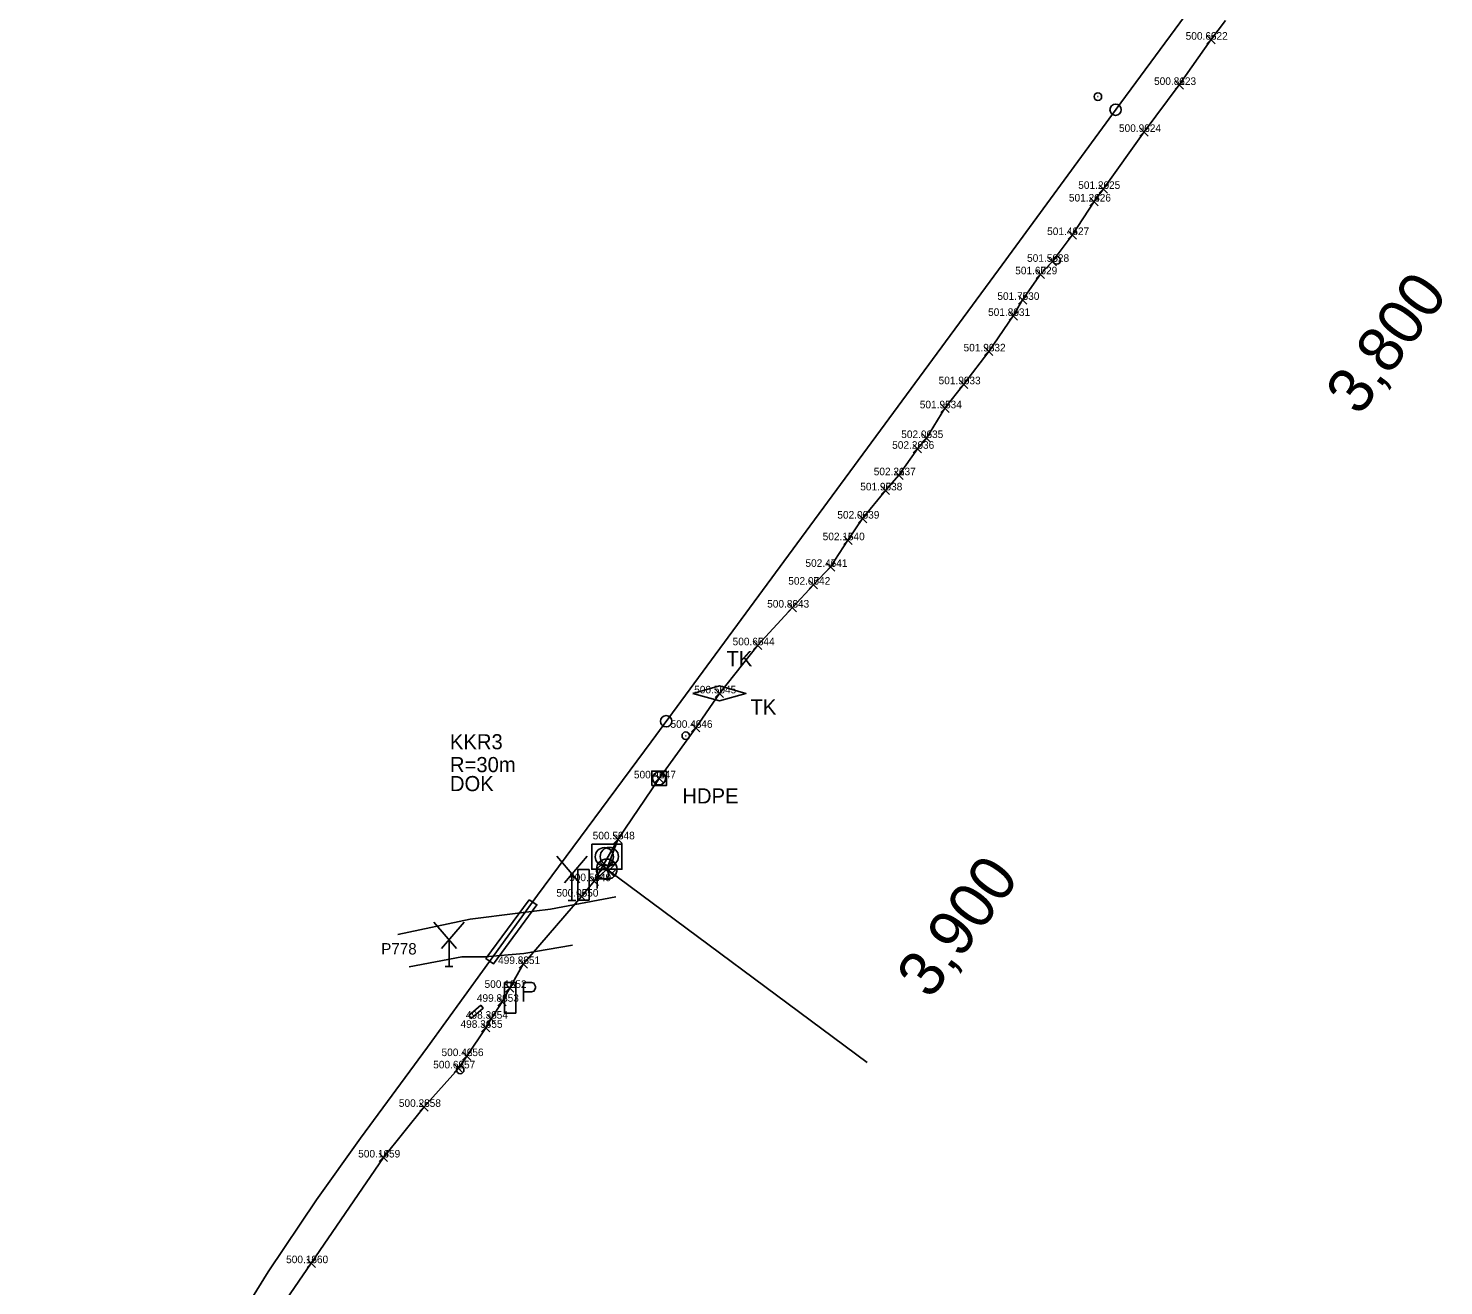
# Model space of a CAD drawing. Extents: x -874058 to -854960, y -10531873 to -1049126.
# Drawn here: x -868334.1 to -868146.9, y -1053927.2 to -1053761 of the extents above; entities that cross this region are included whole.
import ezdxf

# ---------------------------------------------------------------- set-up
doc = ezdxf.new("R2010")
doc.units = 0
for name, color, linetype in [('Vrstva 1', 7, 'Continuous'), ('Vrstva 18', 7, 'Continuous'), ('Vrstva 30', 7, 'Continuous'), ('Vrstva 31', 7, 'Continuous'), ('Vrstva 32', 7, 'Continuous'), ('Vrstva 33', 7, 'Continuous'), ('Vrstva 35', 7, 'Continuous'), ('Vrstva 4', 7, 'Continuous'), ('Vrstva 51', 7, 'Continuous'), ('Vrstva 53', 7, 'Continuous'), ('Vrstva 60', 7, 'Continuous'), ('Vrstva 61', 7, 'Continuous'), ('Vrstva 7', 7, 'Continuous')]:
    doc.layers.add(name, color=color, linetype=linetype)

msp = doc.modelspace()

# ---------------------------------------------------------------- linework, layer by layer
at = {"layer": 'Vrstva 1'}
msp.add_lwpolyline([(-868334.08, -1053989.14), (-868331.21, -1053981.52), (-868326.64, -1053970.33), (-868321.22, -1053958.73), (-868315.73, -1053947.91), (-868309.42, -1053936.78), (-868302.36, -1053925.35), (-868295.97, -1053915.83), (-868290.16, -1053907.67), (-868281.31, -1053895.65), (-868266.75, -1053875.56), (-868251.72, -1053855.3), (-868231.85, -1053828.28), (-868205.77, -1053792.93), (-868190.24, -1053771.67), (-868167.56, -1053740.94)], dxfattribs=at)
at = {"layer": 'Vrstva 18'}
for points in [[(-868275.83, -1053891.48), (-868274.26, -1053890.12)], [(-868275.83, -1053891.48), (-868275.5, -1053891.86), (-868273.93, -1053890.5), (-868274.26, -1053890.12)]]:
    msp.add_lwpolyline(points, dxfattribs=at)
at = {"layer": 'Vrstva 30'}
msp.add_lwpolyline([(-868251.63, -1053861.09), (-868249.71, -1053861.09), (-868249.71, -1053859.17), (-868251.63, -1053859.17)], close=True, dxfattribs=at)
msp.add_circle((-868250.67, -1053860.13), 0.864, dxfattribs=at)
at = {"layer": 'Vrstva 31'}
for p, q in [((-868258.94, -1053872.14), (-868258.26, -1053871.46)), ((-868258.77, -1053872.78), (-868257.86, -1053871.87)), ((-868258.12, -1053871.74), (-868257.58, -1053872.14)), ((-868257.36, -1053872.36), (-868256.44, -1053871.44)), ((-868256.64, -1053871.18), (-868256.64, -1053871.18)), ((-868256.64, -1053871.18), (-868256.64, -1053871.18)), ((-868258.56, -1053873.09), (-868258.56, -1053873.09)), ((-868258.56, -1053873.09), (-868258.56, -1053873.09)), ((-868256.96, -1053872.76), (-868256.25, -1053872.05)), ((-868256.63, -1053873.09), (-868256.63, -1053873.09))]:
    msp.add_line(p, q, dxfattribs=at)
for points in [[(-868258.54, -1053871.18), (-868257.6, -1053872.14), (-868258.56, -1053873.09)], [(-868256.64, -1053871.18), (-868257.59, -1053872.14), (-868256.63, -1053873.09)]]:
    msp.add_lwpolyline(points, dxfattribs=at)
for centre, start, end in [((-868257.6, -1053872.14), 134.5239, 224.7609), ((-868257.58, -1053872.14), 45.4761, 134.8422), ((-868257.58, -1053872.14), 315.2391, 45.4761), ((-868257.6, -1053872.14), 224.7623, 315.5517)]:
    msp.add_arc(centre, 1.35, start, end, dxfattribs=at)
at = {"layer": 'Vrstva 32'}
msp.add_line((-868257.66, -1053869.31), (-868257.62, -1053869.32), dxfattribs=at)
for points in [[(-868175.77, -1053759.96), (-868177.71, -1053762.5), (-868181.89, -1053768.48), (-868186.53, -1053774.69), (-868191.92, -1053782.22), (-868193.15, -1053783.89), (-868196.03, -1053788.32), (-868198.68, -1053791.86), (-868200.25, -1053793.51), (-868202.61, -1053796.89), (-868203.84, -1053799.01), (-868207.08, -1053803.7), (-868210.38, -1053808.04), (-868212.87, -1053811.22), (-868215.32, -1053815.15), (-868216.52, -1053816.57), (-868218.96, -1053820.07), (-868220.74, -1053822.07), (-868223.77, -1053825.8), (-868225.71, -1053828.66), (-868227.99, -1053832.18), (-868230.26, -1053834.53), (-868233.05, -1053837.56), (-868237.62, -1053842.54), (-868242.7, -1053848.9), (-868245.83, -1053853.45), (-868250.67, -1053860.13), (-868256.12, -1053868.19)], [(-868246.2, -1053848.9), (-868242.7, -1053847.9), (-868239.2, -1053848.9), (-868242.7, -1053849.9), (-868246.2, -1053848.9)], [(-868256.12, -1053868.19), (-868259.24, -1053873.72)], [(-868256.12, -1053868.19), (-868257.58, -1053872.14)], [(-868259.24, -1053873.72), (-868260.92, -1053875.76), (-868268.63, -1053884.67), (-868270.42, -1053887.82), (-868271.44, -1053889.66), (-868272.89, -1053891.9), (-868273.6, -1053893.1), (-868276.11, -1053896.84), (-868277.21, -1053898.46), (-868281.75, -1053903.55), (-868287.13, -1053910.24), (-868296.66, -1053924.21), (-868301.1, -1053930.62), (-868304.54, -1053937.27), (-868305.92, -1053938.83), (-868307.71, -1053941.38), (-868311.9, -1053949.06), (-868314.21, -1053952.75), (-868319.28, -1053963.96), (-868324.77, -1053976.84), (-868327.22, -1053982.17), (-868329.01, -1053985.82), (-868329.51, -1053986.53)], [(-868257.58, -1053872.14), (-868259.24, -1053873.72)]]:
    msp.add_lwpolyline(points, dxfattribs=at)
msp.add_lwpolyline([(-868259.58, -1053868.81), (-868255.59, -1053868.81), (-868255.59, -1053872.14), (-868259.58, -1053872.14)], close=True, dxfattribs=at)
for centre in [(-868257.91, -1053870.49), (-868257.25, -1053870.46)]:
    msp.add_circle(centre, 1.2, dxfattribs=at)
at = {"layer": 'Vrstva 33'}
for points in [[(-868261.42, -1053872.19), (-868259.93, -1053872.19), (-868259.93, -1053876.22), (-868261.42, -1053876.22)], [(-868271.11, -1053887.12), (-868269.62, -1053887.12), (-868269.62, -1053891.15), (-868271.11, -1053891.15)]]:
    msp.add_lwpolyline(points, close=True, dxfattribs=at)
for points in [[(-868258.88, -1053874.69), (-868258.88, -1053872.18)], [(-868258.88, -1053872.18), (-868257.84, -1053872.18)], [(-868257.84, -1053873.42), (-868258.88, -1053873.42)], [(-868257.84, -1053872.18), (-868257.52, -1053872.29), (-868257.3, -1053872.7), (-868257.3, -1053872.92), (-868257.52, -1053873.33), (-868257.84, -1053873.42)], [(-868268.58, -1053889.62), (-868268.58, -1053887.11)], [(-868268.58, -1053887.11), (-868267.53, -1053887.11)], [(-868267.53, -1053888.35), (-868268.58, -1053888.35)], [(-868267.53, -1053887.11), (-868267.22, -1053887.21), (-868267, -1053887.62), (-868267, -1053887.84), (-868267.22, -1053888.26), (-868267.53, -1053888.35)]]:
    msp.add_lwpolyline(points, dxfattribs=at)
at = {"layer": 'Vrstva 35'}
msp.add_lwpolyline([(-868260.92, -1053875.76), (-868268.63, -1053884.67)], dxfattribs=at)
at = {"layer": 'Vrstva 4'}
for p, q in [((-868264.2, -1053870.42), (-868261.2, -1053873.92)), ((-868263.2, -1053873.92), (-868260.2, -1053870.42)), ((-868262.2, -1053876.27), (-868262.2, -1053872.77)), ((-868262.7, -1053876.27), (-868261.7, -1053876.27)), ((-868280.45, -1053879.13), (-868277.45, -1053882.63)), ((-868279.45, -1053882.63), (-868276.45, -1053879.13)), ((-868278.45, -1053884.98), (-868278.45, -1053881.48)), ((-868278.95, -1053884.98), (-868277.95, -1053884.98))]:
    msp.add_line(p, q, dxfattribs=at)
at = {"layer": 'Vrstva 51'}
for points in [[(-868285.22, -1053880.77), (-868275.66, -1053878.75), (-868269.37, -1053877.94), (-868265.03, -1053877.42), (-868256.39, -1053875.8)], [(-868267.84, -1053876.18), (-868273.56, -1053883.93), (-868272.58, -1053884.65), (-868266.82, -1053876.84), (-868267.84, -1053876.18)], [(-868283.72, -1053885.02), (-868276.76, -1053883.74), (-868273.71, -1053883.74), (-868268.56, -1053883.26), (-868262.1, -1053882.19)]]:
    msp.add_lwpolyline(points, dxfattribs=at)
at = {"layer": 'Vrstva 53'}
for p, q in [((-868198.13, -1053791.67), (-868198.03, -1053791.67)), ((-868277.02, -1053898.67), (-868276.92, -1053898.67))]:
    msp.add_line(p, q, dxfattribs=at)
for centre in [(-868198.08, -1053791.67), (-868276.97, -1053898.67)]:
    msp.add_circle(centre, 0.499, dxfattribs=at)
at = {"layer": 'Vrstva 60'}
for p, q in [((-868178.26, -1053763.05), (-868177.16, -1053761.95)), ((-868177.16, -1053763.05), (-868178.26, -1053761.95)), ((-868182.44, -1053769.03), (-868181.34, -1053767.93)), ((-868181.34, -1053769.03), (-868182.44, -1053767.93)), ((-868187.08, -1053775.24), (-868185.98, -1053774.14)), ((-868185.98, -1053775.24), (-868187.08, -1053774.14)), ((-868192.47, -1053782.77), (-868191.37, -1053781.67)), ((-868191.37, -1053782.77), (-868192.47, -1053781.67)), ((-868193.7, -1053784.44), (-868192.6, -1053783.34)), ((-868192.6, -1053784.44), (-868193.7, -1053783.34)), ((-868196.58, -1053788.87), (-868195.48, -1053787.77)), ((-868195.48, -1053788.87), (-868196.58, -1053787.77)), ((-868199.23, -1053792.41), (-868198.13, -1053791.31)), ((-868198.13, -1053792.41), (-868199.23, -1053791.31)), ((-868200.8, -1053794.06), (-868199.7, -1053792.96)), ((-868199.7, -1053794.06), (-868200.8, -1053792.96)), ((-868203.16, -1053797.44), (-868202.06, -1053796.34)), ((-868202.06, -1053797.44), (-868203.16, -1053796.34)), ((-868204.39, -1053799.56), (-868203.29, -1053798.46)), ((-868203.29, -1053799.56), (-868204.39, -1053798.46)), ((-868207.63, -1053804.25), (-868206.53, -1053803.15)), ((-868206.53, -1053804.25), (-868207.63, -1053803.15)), ((-868210.93, -1053808.59), (-868209.83, -1053807.49)), ((-868209.83, -1053808.59), (-868210.93, -1053807.49)), ((-868213.42, -1053811.77), (-868212.32, -1053810.67)), ((-868212.32, -1053811.77), (-868213.42, -1053810.67)), ((-868215.87, -1053815.7), (-868214.77, -1053814.6)), ((-868214.77, -1053815.7), (-868215.87, -1053814.6)), ((-868217.07, -1053817.12), (-868215.97, -1053816.02)), ((-868215.97, -1053817.12), (-868217.07, -1053816.02)), ((-868219.51, -1053820.62), (-868218.41, -1053819.52)), ((-868218.41, -1053820.62), (-868219.51, -1053819.52)), ((-868221.29, -1053822.62), (-868220.19, -1053821.52)), ((-868220.19, -1053822.62), (-868221.29, -1053821.52)), ((-868224.32, -1053826.35), (-868223.22, -1053825.25)), ((-868223.22, -1053826.35), (-868224.32, -1053825.25)), ((-868226.26, -1053829.21), (-868225.16, -1053828.11)), ((-868225.16, -1053829.21), (-868226.26, -1053828.11)), ((-868228.54, -1053832.73), (-868227.44, -1053831.63)), ((-868227.44, -1053832.73), (-868228.54, -1053831.63)), ((-868230.81, -1053835.08), (-868229.71, -1053833.98)), ((-868229.71, -1053835.08), (-868230.81, -1053833.98)), ((-868233.6, -1053838.11), (-868232.5, -1053837.01)), ((-868232.5, -1053838.11), (-868233.6, -1053837.01)), ((-868238.17, -1053843.09), (-868237.07, -1053841.99)), ((-868237.07, -1053843.09), (-868238.17, -1053841.99)), ((-868243.25, -1053849.45), (-868242.15, -1053848.35)), ((-868242.15, -1053849.45), (-868243.25, -1053848.35)), ((-868246.38, -1053854), (-868245.28, -1053852.9)), ((-868245.28, -1053854), (-868246.38, -1053852.9)), ((-868251.22, -1053860.68), (-868250.12, -1053859.58)), ((-868250.12, -1053860.68), (-868251.22, -1053859.58)), ((-868256.67, -1053868.74), (-868255.57, -1053867.64)), ((-868255.57, -1053868.74), (-868256.67, -1053867.64)), ((-868259.79, -1053874.27), (-868258.69, -1053873.17)), ((-868258.69, -1053874.27), (-868259.79, -1053873.17)), ((-868261.47, -1053876.31), (-868260.37, -1053875.21)), ((-868260.37, -1053876.31), (-868261.47, -1053875.21)), ((-868269.18, -1053885.22), (-868268.08, -1053884.12)), ((-868268.08, -1053885.22), (-868269.18, -1053884.12)), ((-868270.97, -1053888.37), (-868269.87, -1053887.27)), ((-868269.87, -1053888.37), (-868270.97, -1053887.27)), ((-868271.99, -1053890.21), (-868270.89, -1053889.11)), ((-868270.89, -1053890.21), (-868271.99, -1053889.11)), ((-868274.15, -1053893.65), (-868273.05, -1053892.55)), ((-868273.05, -1053893.65), (-868274.15, -1053892.55)), ((-868273.44, -1053892.45), (-868272.34, -1053891.35)), ((-868272.34, -1053892.45), (-868273.44, -1053891.35)), ((-868276.66, -1053897.39), (-868275.56, -1053896.29)), ((-868275.56, -1053897.39), (-868276.66, -1053896.29)), ((-868277.76, -1053899.01), (-868276.66, -1053897.91)), ((-868276.66, -1053899.01), (-868277.76, -1053897.91)), ((-868282.3, -1053904.1), (-868281.2, -1053903)), ((-868281.2, -1053904.1), (-868282.3, -1053903)), ((-868287.68, -1053910.79), (-868286.58, -1053909.69)), ((-868286.58, -1053910.79), (-868287.68, -1053909.69)), ((-868297.21, -1053924.76), (-868296.11, -1053923.66)), ((-868296.11, -1053924.76), (-868297.21, -1053923.66))]:
    msp.add_line(p, q, dxfattribs=at)
at = {"layer": 'Vrstva 7'}
for p, q in [((-868192.7, -1053770.03), (-868192.6, -1053770.03)), ((-868247.19, -1053854.49), (-868247.09, -1053854.49)), ((-868223.14, -1053897.69), (-868257.58, -1053872.14))]:
    msp.add_line(p, q, dxfattribs=at)
for centre, radius in [((-868192.65, -1053770.03), 0.5), ((-868190.31, -1053771.76), 0.75), ((-868249.73, -1053852.59), 0.75), ((-868247.14, -1053854.49), 0.5)]:
    msp.add_circle(centre, radius, dxfattribs=at)

# ---------------------------------------------------------------- texts
at = {"layer": 'Vrstva 32'}
for s, p in [('TK', (-868241.77, -1053845.31)), ('TK', (-868238.59, -1053851.69)), ('KKR3', (-868278.33, -1053856.29)), ('R=30m', (-868278.33, -1053859.31)), ('DOK', (-868278.33, -1053861.82)), ('HDPE', (-868247.6, -1053863.45))]:
    msp.add_text(s, height=2, dxfattribs=at).set_placement(p)
at = {"layer": 'Vrstva 4'}
msp.add_text('P778', height=1.5, dxfattribs=at).set_placement((-868287.41, -1053883.41))
at = {"layer": 'Vrstva 60'}
for s, p in [('622', (-868177.71, -1053762.5)), ('623', (-868181.89, -1053768.48)), ('624', (-868186.53, -1053774.69)), ('625', (-868191.92, -1053782.22)), ('626', (-868193.15, -1053783.89)), ('627', (-868196.03, -1053788.32)), ('628', (-868198.68, -1053791.86)), ('629', (-868200.25, -1053793.51)), ('630', (-868202.61, -1053796.89)), ('631', (-868203.84, -1053799.01)), ('632', (-868207.08, -1053803.7)), ('633', (-868210.38, -1053808.04)), ('634', (-868212.87, -1053811.22)), ('636', (-868216.52, -1053816.57)), ('635', (-868215.32, -1053815.15)), ('637', (-868218.96, -1053820.07)), ('638', (-868220.74, -1053822.07)), ('639', (-868223.77, -1053825.8)), ('640', (-868225.71, -1053828.66)), ('641', (-868227.99, -1053832.18)), ('642', (-868230.26, -1053834.53)), ('643', (-868233.05, -1053837.56)), ('644', (-868237.62, -1053842.54)), ('645', (-868242.7, -1053848.9)), ('646', (-868245.83, -1053853.45)), ('647', (-868250.67, -1053860.13)), ('648', (-868256.12, -1053868.19)), ('649', (-868259.24, -1053873.72)), ('650', (-868260.92, -1053875.76)), ('651', (-868268.63, -1053884.67)), ('652', (-868270.42, -1053887.82)), ('653', (-868271.44, -1053889.66)), ('655', (-868273.6, -1053893.1)), ('654', (-868272.89, -1053891.9)), ('656', (-868276.11, -1053896.84)), ('657', (-868277.21, -1053898.46)), ('658', (-868281.75, -1053903.55)), ('659', (-868287.13, -1053910.24)), ('660', (-868296.66, -1053924.21))]:
    msp.add_text(s, height=1, dxfattribs=at).set_placement(p)
at = {"layer": 'Vrstva 61'}
for s, p in [('500.63 ', (-868181.04, -1053762.5)), ('500.81 ', (-868185.22, -1053768.48)), ('500.96 ', (-868189.86, -1053774.69)), ('501.20 ', (-868195.25, -1053782.22)), ('501.24 ', (-868196.48, -1053783.89)), ('501.44 ', (-868199.36, -1053788.32)), ('501.56 ', (-868202.01, -1053791.86)), ('501.67 ', (-868203.58, -1053793.51)), ('501.75 ', (-868205.94, -1053796.89)), ('501.80 ', (-868207.17, -1053799.01)), ('501.93 ', (-868210.41, -1053803.7)), ('501.99 ', (-868213.71, -1053808.04)), ('501.95 ', (-868216.2, -1053811.22)), ('502.20 ', (-868219.85, -1053816.57)), ('502.06 ', (-868218.65, -1053815.15)), ('502.21 ', (-868222.29, -1053820.07)), ('501.95 ', (-868224.07, -1053822.07)), ('502.00 ', (-868227.1, -1053825.8)), ('502.15 ', (-868229.04, -1053828.66)), ('502.47 ', (-868231.32, -1053832.18)), ('502.07 ', (-868233.59, -1053834.53)), ('500.83 ', (-868236.38, -1053837.56)), ('500.65 ', (-868240.95, -1053842.54)), ('500.50 ', (-868246.03, -1053848.9)), ('500.43 ', (-868249.16, -1053853.45)), ('500.44 ', (-868254, -1053860.13)), ('500.53 ', (-868259.45, -1053868.19)), ('500.50 ', (-868262.57, -1053873.72)), ('500.05 ', (-868264.25, -1053875.76)), ('499.83 ', (-868271.96, -1053884.67)), ('500.12 ', (-868273.75, -1053887.82)), ('499.88 ', (-868274.77, -1053889.66)), ('498.34 ', (-868276.93, -1053893.1)), ('498.38 ', (-868276.22, -1053891.9)), ('500.42 ', (-868279.44, -1053896.84)), ('500.62 ', (-868280.54, -1053898.46)), ('500.28 ', (-868285.08, -1053903.55)), ('500.14 ', (-868290.46, -1053910.24)), ('500.13 ', (-868299.99, -1053924.21))]:
    msp.add_text(s, height=1, dxfattribs=at).set_placement(p)
at = {"layer": 'Vrstva 7'}
for s, rotation, p in [('3,800', 53.8526, (-868158.07, -1053812.39)), ('3,900', 53.6699, (-868214.81, -1053889.49))]:
    msp.add_text(s, height=6, rotation=rotation, dxfattribs=at).set_placement(p)

doc.saveas('drawing.dxf')
